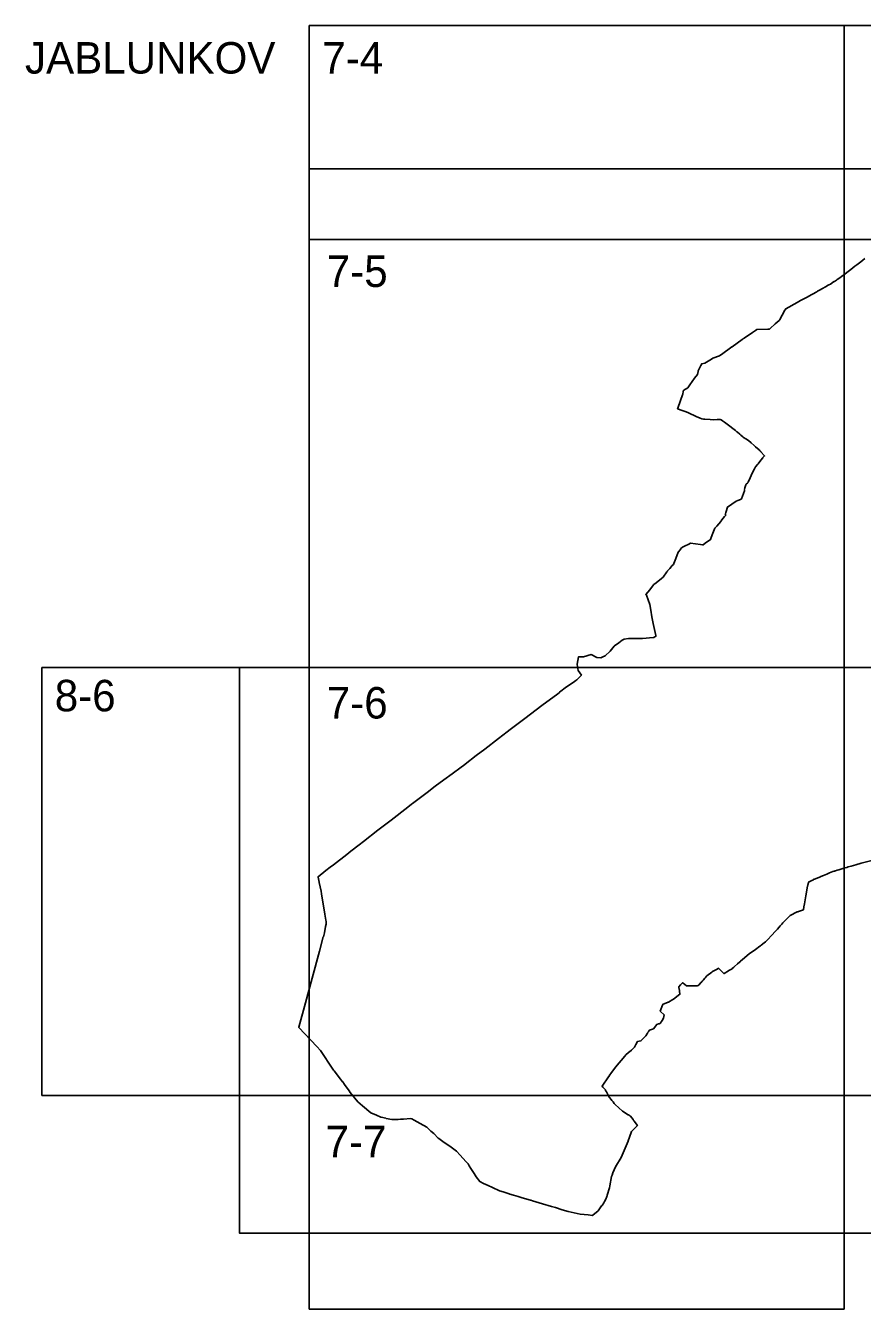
# Model space of a CAD drawing. Extents: x -449577 to -436680, y -1132317 to -1125726.
# Drawn here: x -444051.3 to -443806.9, y -1130325 to -1129950 of the extents above; entities that cross this region are included whole.
import ezdxf

# ---------------------------------------------------------------- set-up
doc = ezdxf.new("R2010")
doc.units = 0
for name, color, linetype in [('Vrstva 1', 7, 'Continuous'), ('Vrstva 10', 7, 'Continuous'), ('Vrstva 4', 7, 'Continuous')]:
    doc.layers.add(name, color=color, linetype=linetype)

msp = doc.modelspace()

# ---------------------------------------------------------------- linework, layer by layer
at = {"layer": 'Vrstva 1'}
for points in [[(-443806.12, -1130018), (-443807.33, -1130018.96), (-443807.33, -1130018.96), (-443808.48, -1130019.83), (-443809.05, -1130020.26), (-443809.63, -1130020.7), (-443809.79, -1130020.82), (-443811.92, -1130022.46), (-443812.99, -1130023.28), (-443813.46, -1130023.62), (-443814.22, -1130024.13), (-443814.47, -1130024.29), (-443815.06, -1130024.68), (-443815.1, -1130024.71), (-443815.31, -1130024.85), (-443816.22, -1130025.45), (-443816.23, -1130025.45), (-443816.7, -1130025.71), (-443816.85, -1130025.79), (-443817.03, -1130025.89), (-443817.49, -1130026.14), (-443817.67, -1130026.25), (-443817.83, -1130026.34), (-443817.93, -1130026.4), (-443818.17, -1130026.54), (-443819.83, -1130027.48), (-443820, -1130027.57), (-443820.23, -1130027.7), (-443822.7, -1130029.1), (-443822.82, -1130029.17), (-443824.93, -1130030.3), (-443825.95, -1130030.85), (-443829.29, -1130032.66), (-443829.46, -1130032.96), (-443829.52, -1130033.07), (-443830.3, -1130034.53), (-443830.98, -1130035.85), (-443831.12, -1130035.98), (-443831.21, -1130036.06), (-443832.35, -1130037.1), (-443833.86, -1130038.48), (-443834.03, -1130038.63), (-443834.03, -1130038.64), (-443834.5, -1130038.65), (-443837.69, -1130038.74), (-443837.7, -1130038.74), (-443838.13, -1130039.03), (-443838.96, -1130039.6), (-443841.43, -1130041.26), (-443841.47, -1130041.28), (-443841.71, -1130041.46), (-443841.98, -1130041.66), (-443844.96, -1130043.79), (-443845.03, -1130043.84), (-443848.03, -1130046.02), (-443848.5, -1130046.36), (-443848.66, -1130046.42), (-443850.6, -1130047.14), (-443850.61, -1130047.14), (-443851, -1130047.38), (-443852.88, -1130048.54), (-443853.8, -1130048.75), (-443854.05, -1130049.26), (-443854.81, -1130050.77), (-443854.82, -1130050.78), (-443854.89, -1130051.04), (-443855.09, -1130051.88), (-443855.92, -1130052.99), (-443857.29, -1130054.94), (-443857.85, -1130055.75), (-443857.88, -1130055.77), (-443859.04, -1130056.41), (-443859.14, -1130056.47), (-443859.21, -1130056.86), (-443859.36, -1130057.67), (-443859.41, -1130057.86), (-443860.7, -1130061.44), (-443860.87, -1130061.92), (-443860.84, -1130061.91), (-443860.82, -1130061.9), (-443860.14, -1130062.16), (-443858.33, -1130062.82), (-443857.71, -1130063.11), (-443855.42, -1130064.19), (-443855.4, -1130064.19), (-443854.24, -1130064.66), (-443853.77, -1130064.84), (-443853.74, -1130064.85), (-443853.31, -1130064.88), (-443853.17, -1130064.89), (-443852.95, -1130064.91), (-443851.35, -1130065.01), (-443850.31, -1130065.08), (-443849.26, -1130065.05), (-443848.42, -1130065.02), (-443848.41, -1130065.02), (-443848.13, -1130065.17), (-443847.76, -1130065.43), (-443847.21, -1130065.81), (-443846.82, -1130066.09), (-443845.26, -1130067.23), (-443845.09, -1130067.35), (-443843.98, -1130068.27), (-443843.59, -1130068.59), (-443843.41, -1130068.74), (-443842.66, -1130069.35), (-443842.39, -1130069.58), (-443841.79, -1130070.07), (-443841.57, -1130070.25), (-443840.93, -1130070.67), (-443840.18, -1130071.17), (-443840.15, -1130071.19), (-443839.39, -1130071.87), (-443838.51, -1130072.65), (-443838.07, -1130073.03), (-443837.06, -1130073.92), (-443836.8, -1130074.15), (-443836.75, -1130074.2), (-443836.65, -1130074.3), (-443836.64, -1130074.31), (-443836.55, -1130074.41), (-443836.52, -1130074.44), (-443835.47, -1130075.67), (-443835.48, -1130075.68), (-443835.92, -1130076.17), (-443835.98, -1130076.24), (-443836.55, -1130076.87), (-443837.37, -1130077.93), (-443837.54, -1130078.14), (-443838.1, -1130078.86), (-443838.4, -1130079.39), (-443838.42, -1130079.43), (-443838.43, -1130079.45), (-443838.56, -1130079.73), (-443839.36, -1130081.4), (-443839.67, -1130082.04), (-443840.29, -1130083.33), (-443840.4, -1130083.57), (-443840.41, -1130083.57), (-443840.45, -1130083.6), (-443840.74, -1130083.8), (-443840.82, -1130083.84), (-443840.87, -1130083.94), (-443840.96, -1130084.14), (-443841.05, -1130084.42), (-443841.22, -1130084.98), (-443841.23, -1130085), (-443841.35, -1130085.5), (-443841.37, -1130085.57), (-443841.36, -1130085.63), (-443841.35, -1130085.71), (-443841.35, -1130085.78), (-443841.36, -1130085.83), (-443842.24, -1130088.16), (-443842.26, -1130088.21), (-443842.28, -1130088.25), (-443842.29, -1130088.26), (-443842.99, -1130088.56), (-443843.24, -1130088.67), (-443843.71, -1130088.91), (-443846.32, -1130090.6), (-443846.32, -1130090.6), (-443846.69, -1130091.91), (-443846.77, -1130092.17), (-443846.88, -1130092.59), (-443846.94, -1130092.8), (-443846.94, -1130092.81), (-443846.93, -1130092.81), (-443846.76, -1130092.97), (-443846.77, -1130092.98), (-443847.13, -1130093.37), (-443847.93, -1130094.37), (-443847.94, -1130094.38), (-443848.15, -1130094.63), (-443848.15, -1130094.64), (-443848.27, -1130094.79), (-443849.43, -1130096.14), (-443849.97, -1130096.77), (-443850.73, -1130098.72), (-443851.11, -1130099.74), (-443851.24, -1130100.09), (-443852.77, -1130101.19), (-443853.39, -1130101.63), (-443853.57, -1130101.67), (-443853.59, -1130101.67), (-443854.22, -1130101.58), (-443857.06, -1130101.16), (-443857.55, -1130101.4), (-443858.88, -1130102.04), (-443859.42, -1130102.3), (-443859.45, -1130102.33), (-443859.88, -1130102.74), (-443860.05, -1130102.96), (-443860.71, -1130103.81), (-443860.71, -1130103.82), (-443861.38, -1130105.62), (-443861.95, -1130107.12), (-443861.95, -1130107.12), (-443862.09, -1130107.34), (-443862.42, -1130107.71), (-443863.14, -1130108.51), (-443863.84, -1130109.28), (-443863.85, -1130109.3), (-443863.98, -1130109.49), (-443865.05, -1130111.06), (-443865.52, -1130111.44), (-443867.09, -1130112.7), (-443867.76, -1130113.24), (-443867.86, -1130113.32), (-443867.89, -1130113.36), (-443869.01, -1130114.79), (-443870.15, -1130116.1), (-443870, -1130116.27), (-443869.99, -1130116.3), (-443869.99, -1130116.31), (-443868.98, -1130119.07), (-443868.7, -1130120.73), (-443868.38, -1130122.68), (-443867.97, -1130124.64), (-443867.24, -1130128.14), (-443867.2, -1130128.34), (-443867.85, -1130128.68), (-443867.97, -1130128.75), (-443871.14, -1130129.01), (-443871.3, -1130129.01), (-443872.79, -1130128.98), (-443875.18, -1130128.96), (-443876.46, -1130129.23), (-443877.06, -1130129.5), (-443878.04, -1130130.3), (-443879.34, -1130131.17), (-443879.43, -1130131.28), (-443880.59, -1130132.7), (-443882.04, -1130134.04), (-443882.73, -1130134.36), (-443883.33, -1130134.64), (-443884.5, -1130134.57), (-443886.11, -1130133.72), (-443888.35, -1130134.39), (-443889.83, -1130134.36), (-443890.21, -1130136.47), (-443890.22, -1130136.49), (-443890.23, -1130136.58), (-443889.94, -1130138.39), (-443888.97, -1130139.71), (-443888.96, -1130139.73), (-443889.7, -1130140.48), (-443890.31, -1130141.04), (-443890.56, -1130141.27), (-443891.36, -1130141.9), (-443893.29, -1130143.13), (-443893.35, -1130143.17), (-443895.32, -1130144.7), (-443895.38, -1130144.74), (-443895.87, -1130145.12), (-443900.53, -1130148.58), (-443900.56, -1130148.61), (-443905.51, -1130152.37), (-443909.77, -1130155.62), (-443910.65, -1130156.28), (-443913.22, -1130158.22), (-443917.22, -1130161.35), (-443919.66, -1130163.22), (-443922.97, -1130165.75), (-443923.02, -1130165.79), (-443927.81, -1130169.3), (-443928.04, -1130169.48), (-443931.65, -1130172.16), (-443934.04, -1130173.98), (-443936.01, -1130175.46), (-443938.33, -1130177.21), (-443938.56, -1130177.38), (-443939.69, -1130178.27), (-443944.51, -1130182.07), (-443948.4, -1130185.02), (-443952.62, -1130188.27), (-443953.91, -1130189.27), (-443956.3, -1130191.15), (-443957.48, -1130192.07), (-443961.42, -1130195.12), (-443962.35, -1130195.83), (-443963.59, -1130196.79), (-443965.91, -1130198.59), (-443965.91, -1130198.59), (-443965.87, -1130198.77), (-443965.58, -1130200.15), (-443965.55, -1130200.31), (-443965.02, -1130202.85), (-443964.86, -1130203.58), (-443964.86, -1130203.62), (-443963.93, -1130209.5), (-443963.92, -1130209.53), (-443963.62, -1130211.26), (-443963.62, -1130211.28), (-443963.56, -1130211.65), (-443963.5, -1130212.07), (-443963.53, -1130212.44), (-443963.68, -1130213.17), (-443964.06, -1130214.96), (-443964.35, -1130216.14), (-443964.37, -1130216.19), (-443965.48, -1130220.36), (-443967.58, -1130228.24), (-443969.57, -1130235.46), (-443971.5, -1130242.56), (-443971.51, -1130242.6), (-443966.23, -1130248.2), (-443965.18, -1130249.33), (-443964.42, -1130250.55), (-443962.4, -1130253.61), (-443962.35, -1130253.68), (-443961.34, -1130255.09), (-443961.18, -1130255.3), (-443959.3, -1130257.78), (-443958.73, -1130258.52), (-443958.7, -1130258.56), (-443958.18, -1130259.28), (-443956.8, -1130261.18), (-443956.47, -1130261.63), (-443954.32, -1130264.35), (-443952.92, -1130265.57), (-443950.52, -1130267.55), (-443948.78, -1130268.3), (-443947.59, -1130268.82), (-443947.46, -1130268.87), (-443946.13, -1130269.15), (-443945.99, -1130269.18), (-443944.37, -1130269.51), (-443944.34, -1130269.51), (-443943.38, -1130269.49), (-443943, -1130269.49), (-443942.48, -1130269.48), (-443941.8, -1130269.47), (-443940.89, -1130269.43), (-443938.94, -1130269.27), (-443938.49, -1130269.34), (-443937.83, -1130269.69), (-443936.11, -1130270.64), (-443934.15, -1130271.74), (-443933.63, -1130272.22), (-443932.91, -1130272.9), (-443932.11, -1130273.65), (-443930.79, -1130274.95), (-443930.65, -1130275.05), (-443929.46, -1130275.9), (-443927.05, -1130277.61), (-443925.41, -1130278.79), (-443924.36, -1130279.97), (-443922.72, -1130281.79), (-443922.08, -1130282.5), (-443921.72, -1130283.09), (-443921.26, -1130283.83), (-443920.32, -1130285.3), (-443919.69, -1130286.22), (-443918.65, -1130287.66), (-443917.58, -1130288.17), (-443916.2, -1130288.82), (-443914.89, -1130289.43), (-443912.92, -1130290.32), (-443911.79, -1130290.67), (-443910.07, -1130291.24), (-443909.92, -1130291.29), (-443908.83, -1130291.61), (-443907.41, -1130292.03), (-443907.4, -1130292.03), (-443907.19, -1130292.09), (-443907.13, -1130292.11), (-443906.27, -1130292.37), (-443903.88, -1130293.06), (-443903.76, -1130293.1), (-443903.28, -1130293.24), (-443900.35, -1130294.11), (-443897.66, -1130294.94), (-443897.32, -1130295.04), (-443896.56, -1130295.27), (-443894.55, -1130295.89), (-443892.82, -1130296.44), (-443889.36, -1130297.18)], [(-443889.36, -1130297.18), (-443886.97, -1130297.37), (-443885.77, -1130297.6), (-443885.66, -1130297.51), (-443884.08, -1130296.24), (-443883.05, -1130294.76), (-443882.94, -1130294.61), (-443882.42, -1130293.85), (-443882.31, -1130293.68), (-443882.17, -1130293.45), (-443881.79, -1130292.82), (-443881.52, -1130291.99), (-443881.5, -1130291.92), (-443881.48, -1130291.87), (-443881.45, -1130291.76), (-443881.42, -1130291.67), (-443881.42, -1130291.66), (-443880.79, -1130289.46), (-443880.65, -1130288.94), (-443880.2, -1130286.19), (-443880.2, -1130286.19), (-443880.01, -1130285.75), (-443879.75, -1130285.13), (-443878.96, -1130283.3), (-443877.39, -1130280.65), (-443875.64, -1130276.52), (-443875.32, -1130275.88), (-443875.28, -1130275.75), (-443874.89, -1130274.65), (-443874.3, -1130272.98), (-443872.62, -1130271.27), (-443873.55, -1130270.03), (-443873.61, -1130269.94), (-443873.66, -1130269.88), (-443873.69, -1130269.84), (-443873.76, -1130269.74), (-443873.81, -1130269.66), (-443873.89, -1130269.54), (-443874.25, -1130269.02), (-443874.62, -1130268.56), (-443875.19, -1130268.19), (-443875.29, -1130268.13), (-443876.94, -1130267.06), (-443879.13, -1130265.12), (-443879.26, -1130264.95), (-443879.29, -1130264.91), (-443879.37, -1130264.81), (-443879.71, -1130264.39), (-443880.04, -1130263.98), (-443880.3, -1130263.66), (-443880.78, -1130263.07), (-443880.86, -1130262.97), (-443881.36, -1130262.01), (-443881.65, -1130261.45), (-443881.88, -1130261.02), (-443881.93, -1130260.93), (-443881.97, -1130260.88), (-443882.23, -1130260.59), (-443882.43, -1130260.36), (-443882.69, -1130260.07), (-443882.91, -1130259.82), (-443881.05, -1130257.08), (-443880.96, -1130256.96), (-443880.64, -1130256.51), (-443880.32, -1130256.07), (-443878.99, -1130254.24), (-443876.31, -1130250.98), (-443875.96, -1130250.66), (-443875.25, -1130249.96), (-443875.14, -1130249.87), (-443874.95, -1130249.73), (-443874.35, -1130249.25), (-443873.49, -1130248.41), (-443873.08, -1130247.65), (-443872.61, -1130246.78), (-443871.56, -1130246.54), (-443870.16, -1130245.11), (-443869.62, -1130244.26), (-443869.61, -1130244.25), (-443869.61, -1130244.23), (-443869.4, -1130243.9), (-443869.35, -1130243.82), (-443869.11, -1130243.43), (-443867.95, -1130242.99), (-443866.93, -1130241.81), (-443866.4, -1130241.61), (-443866.28, -1130241.56), (-443865.86, -1130241.4), (-443865.64, -1130241.01), (-443865.59, -1130240.92), (-443865.42, -1130240.62), (-443865.01, -1130239.88), (-443864.81, -1130238.97), (-443864.81, -1130238.95), (-443864.8, -1130238.94), (-443865.85, -1130237.95), (-443865.87, -1130237.94), (-443865.88, -1130237.92), (-443865.93, -1130237.88), (-443865.28, -1130236.08), (-443865.21, -1130235.88), (-443865.05, -1130235.82), (-443864.32, -1130235.53), (-443863.63, -1130235.26), (-443863.51, -1130235.21), (-443862.3, -1130234.5), (-443862.18, -1130234.42), (-443862.18, -1130234.42), (-443862.17, -1130234.41), (-443862.05, -1130234.34), (-443860.19, -1130232.94), (-443860.19, -1130232.9), (-443860.22, -1130232.74), (-443860.29, -1130232.26), (-443860.35, -1130231.91), (-443860.45, -1130231.29), (-443860.47, -1130231.18), (-443860.49, -1130231.05), (-443860.51, -1130230.88), (-443860.54, -1130230.74), (-443860, -1130230.18), (-443859.44, -1130229.61), (-443859.4, -1130229.56), (-443859.26, -1130229.66), (-443858.26, -1130230.45), (-443857.58, -1130230.46), (-443857.52, -1130230.46), (-443857.27, -1130230.47), (-443857.11, -1130230.47), (-443855.8, -1130230.49), (-443855.17, -1130230.51), (-443854.9, -1130230.35), (-443854.87, -1130230.33), (-443854.75, -1130230.26), (-443854.61, -1130230.17), (-443854.57, -1130230.14), (-443854.03, -1130229.54), (-443853.92, -1130229.42), (-443853.83, -1130229.32), (-443853.66, -1130229.14), (-443853.58, -1130229.05), (-443853.47, -1130228.93), (-443853.44, -1130228.89), (-443853.41, -1130228.86), (-443853.36, -1130228.8), (-443853.27, -1130228.69), (-443852.87, -1130228.19), (-443852.66, -1130227.93), (-443852.41, -1130227.61), (-443852.3, -1130227.53), (-443850.84, -1130226.46), (-443850.63, -1130226.33), (-443849.27, -1130225.56), (-443848.87, -1130225.33), (-443848.87, -1130225.33), (-443848.73, -1130225.48), (-443848.02, -1130226.19), (-443847.65, -1130226.57), (-443847.47, -1130226.74), (-443847.32, -1130226.89), (-443847.23, -1130226.85), (-443845.95, -1130226.08), (-443845.86, -1130226.03), (-443844.93, -1130225.47), (-443844.89, -1130225.44), (-443844.56, -1130225.15), (-443844.51, -1130225.11), (-443844.34, -1130224.96), (-443844.33, -1130224.95), (-443844.33, -1130224.95), (-443844.29, -1130224.91), (-443844.25, -1130224.87), (-443843.36, -1130224.06), (-443843.34, -1130224.05), (-443842.75, -1130223.51), (-443842.64, -1130223.42), (-443842.53, -1130223.32), (-443842.53, -1130223.32), (-443842.52, -1130223.32), (-443842.52, -1130223.32), (-443842.52, -1130223.31), (-443842.51, -1130223.31), (-443842.5, -1130223.3), (-443842.5, -1130223.3), (-443842.49, -1130223.29), (-443842.49, -1130223.29), (-443842.48, -1130223.29), (-443842.48, -1130223.29), (-443841.9, -1130222.8), (-443839.91, -1130221.12), (-443838.71, -1130220.27), (-443838.59, -1130220.19), (-443838.54, -1130220.15), (-443838.52, -1130220.14), (-443838.47, -1130220.11), (-443838.11, -1130219.84), (-443836.87, -1130218.9), (-443836.69, -1130218.76), (-443836.48, -1130218.6), (-443836.46, -1130218.58), (-443835.58, -1130217.91), (-443835.23, -1130217.64), (-443835.18, -1130217.58), (-443835.09, -1130217.48), (-443834.45, -1130216.8), (-443833.55, -1130215.82), (-443832.19, -1130214.41), (-443831.97, -1130214.18), (-443831.72, -1130213.9), (-443830.88, -1130212.95), (-443830.59, -1130212.63), (-443830.39, -1130212.42), (-443830.1, -1130212.1), (-443828.92, -1130210.91), (-443827.99, -1130209.89), (-443825.93, -1130208.88), (-443825.77, -1130208.83), (-443825.57, -1130208.75), (-443824.13, -1130208.26), (-443823.98, -1130207.39), (-443823.82, -1130206.52), (-443823.4, -1130204.15), (-443823.32, -1130203.68), (-443822.99, -1130201.8), (-443822.79, -1130200.92), (-443822.76, -1130200.8), (-443822.71, -1130200.61), (-443822.7, -1130200.57), (-443822.68, -1130200.5), (-443822.67, -1130200.46), (-443822.66, -1130200.41), (-443822.65, -1130200.37), (-443822.64, -1130200.35), (-443822.58, -1130200.14), (-443821.5, -1130199.6), (-443821.21, -1130199.46), (-443821.19, -1130199.45), (-443820.94, -1130199.32), (-443820.89, -1130199.3), (-443819.12, -1130198.58), (-443819.09, -1130198.57), (-443819.06, -1130198.55), (-443818.26, -1130198.24), (-443817.3, -1130197.84), (-443816.49, -1130197.5), (-443815.55, -1130197.11), (-443815.47, -1130197.08), (-443814.86, -1130196.84), (-443815.01, -1130197), (-443814.77, -1130196.91), (-443814.28, -1130196.71), (-443813.75, -1130196.55), (-443812.05, -1130196.03), (-443811.46, -1130195.86), (-443811.01, -1130195.74), (-443810.12, -1130195.49), (-443808.81, -1130195.11), (-443807.27, -1130194.65), (-443803.73, -1130193.78)]]:
    msp.add_lwpolyline(points, dxfattribs=at)
at = {"layer": 'Vrstva 10'}
msp.add_lwpolyline([(-443655.97, -1129991.79), (-443655.97, -1130302.77), (-443988.84, -1130302.77), (-443988.84, -1130137.47), (-443968.47, -1130137.47), (-443968.47, -1130012.47), (-443968.47, -1129991.79), (-443655.97, -1129991.79)], dxfattribs=at)
at = {"layer": 'Vrstva 4'}
for p, q in [((-443968.47, -1129949.97), (-443655.97, -1129949.97)), ((-444046.6, -1130137.47), (-444046.6, -1130262.47)), ((-443968.47, -1130324.97), (-443812.22, -1130324.97))]:
    msp.add_line(p, q, dxfattribs=at)
for points in [[(-443812.22, -1129949.97), (-443812.22, -1130012.47), (-443968.47, -1130012.47), (-443968.47, -1129949.97)], [(-443655.97, -1129949.97), (-443655.97, -1130012.47), (-443812.22, -1130012.47), (-443812.22, -1129949.97)], [(-444046.6, -1130137.47), (-443968.47, -1130137.47), (-443968.47, -1130262.47), (-444046.6, -1130262.47)], [(-443968.47, -1130324.97), (-443968.47, -1130262.47), (-443812.22, -1130262.47), (-443812.22, -1130324.97)]]:
    msp.add_lwpolyline(points, dxfattribs=at)
for points in [[(-443812.22, -1130012.47), (-443812.22, -1130137.47), (-443968.47, -1130137.47), (-443968.47, -1130012.47)], [(-443655.97, -1130012.47), (-443655.97, -1130137.47), (-443812.22, -1130137.47), (-443812.22, -1130012.47)], [(-443812.22, -1130137.47), (-443812.22, -1130262.47), (-443968.47, -1130262.47), (-443968.47, -1130137.47)], [(-443655.97, -1130137.47), (-443655.97, -1130262.47), (-443812.22, -1130262.47), (-443812.22, -1130137.47)]]:
    msp.add_lwpolyline(points, close=True, dxfattribs=at)

# ---------------------------------------------------------------- texts
at = {"layer": 'Vrstva 1'}
for s, p in [('JABLUNKOV', (-444051.51, -1129963.97)), ('7-4', (-443964.66, -1129963.97)), ('7-5', (-443963.35, -1130026.31)), ('8-6', (-444042.82, -1130150.28)), ('7-6', (-443963.35, -1130152.38)), ('7-7', (-443963.71, -1130280.55))]:
    msp.add_text(s, height=9.2, dxfattribs=at).set_placement(p)

doc.saveas('drawing.dxf')
